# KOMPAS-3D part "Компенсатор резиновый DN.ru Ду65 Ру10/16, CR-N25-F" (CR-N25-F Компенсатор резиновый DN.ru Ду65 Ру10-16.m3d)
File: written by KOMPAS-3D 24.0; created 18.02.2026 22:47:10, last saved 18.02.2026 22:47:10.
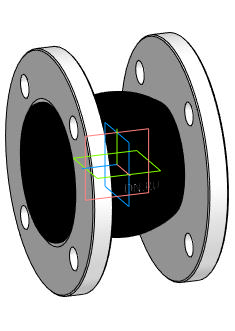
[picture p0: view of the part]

Document properties: Автор: DN.RU; Полное имя файла: D:\PROJECT CAD\DN.RU\...178(1)(ACTUALE). CR-N25-F Компенсатор резиновый DN.ru Ру10-16\DN65\CR-N25-F Компенсатор резиновый DN.ru Ду65 Ру10-16.m3d

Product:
- Body: Твердое тело2  | qty 1
    Масса: 8.739705
- Part/product: Компенсатор резиновый DN.ru Ду65 Ру10/16  | designation CR-N25-F
    Масса: 6
    Раздел спецификации: Прочие изделия
    Комментарий: D140-02392
    Примечание: D140-02392
    additional columns: Типовые

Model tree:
1. Твердое тело2  (labels: Твердое тело2)

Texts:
  CR-N25-F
